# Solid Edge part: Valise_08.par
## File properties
Author: Bernard DUMAS
Template: Normal.par
Last saved by: FR026244
Revision: 12
Application: Solid Edge
Material: Bois, Frêne
Style de face: Jaune kaki
Style de remplissage: Liège
Style virtuel: Frêne verni
Coef. of Thermal Exp: 0.0
Thermal Conductivity: 0.0
Specific Heat: 0.0
Modulus of Elasticity: 0.0
Poission's Ratio: 0.0
Yield Stress: 0.0
Ultimate Stress: 0.0
Elongation: 0.0
Densité: 460.000 kg/m^3
Précision: 0.9900
Document Number: 08
Revision: a
Project Name: Slamson
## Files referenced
..\Valise_Salmson.asm
bD:\Documents and Settings\FR026244\Mes Documents\Bernard\Slamson\Valise-Salmson\Valise_Salmson.asm
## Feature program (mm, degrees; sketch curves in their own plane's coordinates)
sketch for "unnamed Protrusion 1" plane through (0, 0, 0) normal (0, -1, 0) x-axis (1, 0, 0)
extrude "unnamed Protrusion 1" add finite 6 along -normal
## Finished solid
Body 1: solid body, 6 faces, 12 edges, 8 vertices.
  Faces by surface: plane 6
  Edges by curve: line 12
Bounding box of the edges (mm): 447.146 x 6.000 x 54.000, from (-47, 0, 106) to (400.1459, 6, 160).
Planar faces by outward normal: +y 1, +z 1, -x 1, -y 1, -z 1, oblique 1
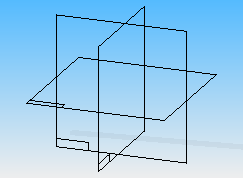
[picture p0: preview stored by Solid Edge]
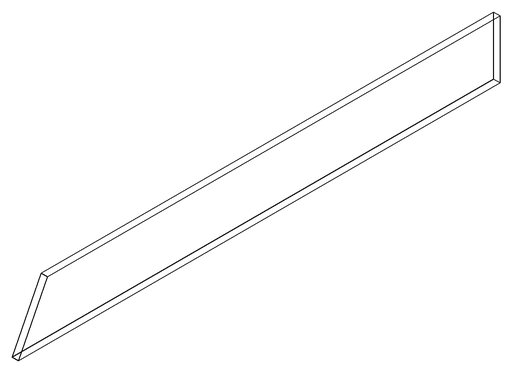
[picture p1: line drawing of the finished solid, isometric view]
